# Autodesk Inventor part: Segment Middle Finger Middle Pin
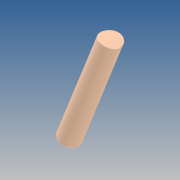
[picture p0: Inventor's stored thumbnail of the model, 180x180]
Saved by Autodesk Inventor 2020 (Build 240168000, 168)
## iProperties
Created: 2019-10
Part Number: Segment Middle Finger Middle Pin
Material: GFRP
Document SubType Name: Modeling
Designer: yello
Density: 1.75 g/cm^3
Appearance: Default
Author: yello
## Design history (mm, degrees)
feature "Paliczek SR"
sketch "Sketch1"
  geometry: C1 r 2 at (0, 0); C2 r 41.214 at (0, 0); 1 further point
  constraints: 2 centre point, 1 coincident
  dimensions: "d0" = 4 diameter of C1
extrude "Extrusion1" cut sketch "Sketch1" stored distance "d1" = 100; taper "d2" = 0 deg
loft "Loft1" dims "d3" = 0, "d4" = 90 deg, "d5" = 0, "d6" = 90 deg
  node "Edges1"
  node "Edges2"
body "Solid1"
